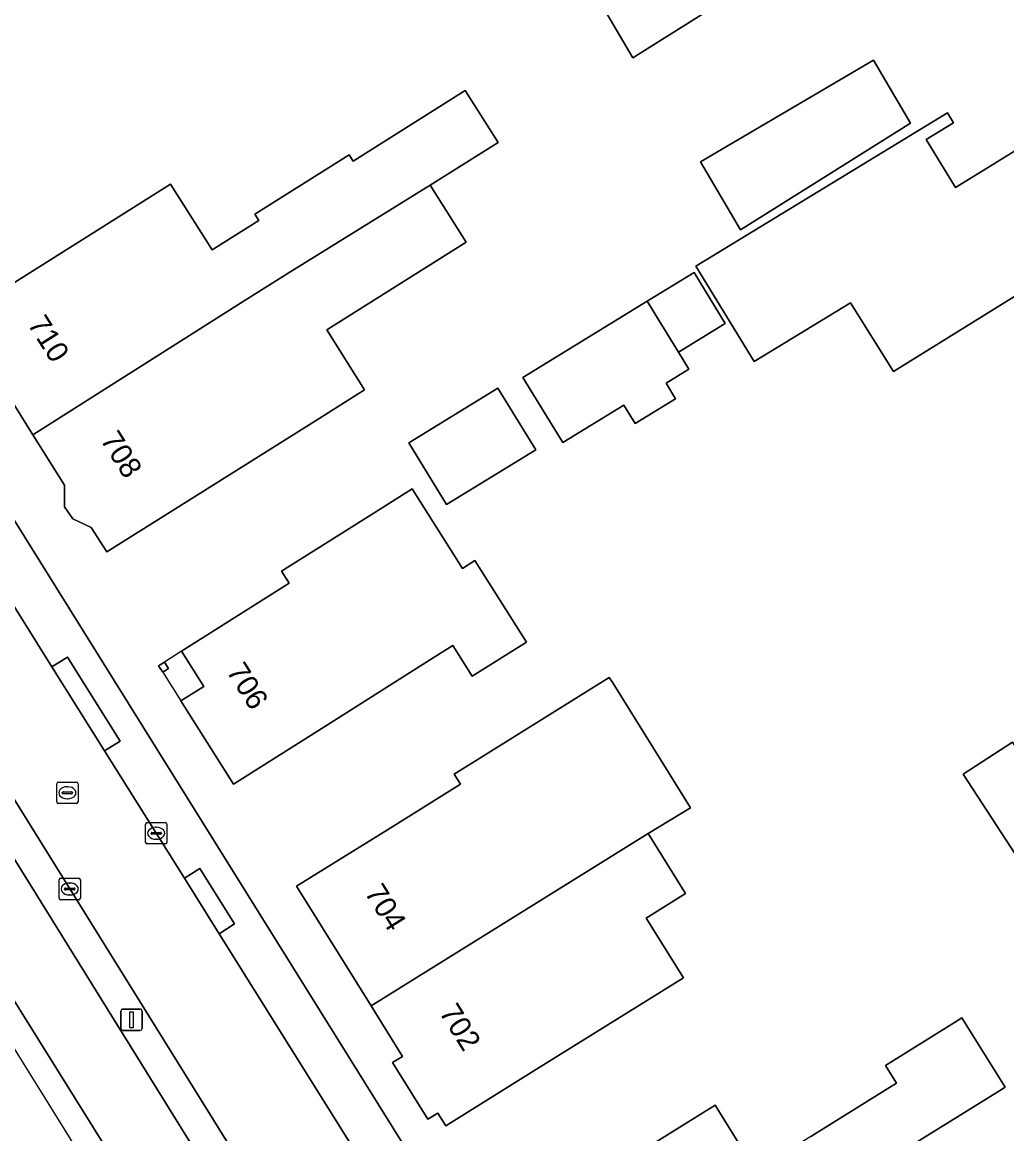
# Model space of a CAD drawing. Extents: x 158835 to 160077, y 386387 to 387778.
# Drawn here: x 159278.9 to 159325, y 386502 to 386554 of the extents above; entities that cross this region are included whole.
import ezdxf

# ---------------------------------------------------------------- set-up
doc = ezdxf.new("R2010")
doc.units = 0
for name, color, linetype in [('IMGEO_Berm_groen', 7, 'Continuous'), ('IMGEO_Erf', 7, 'Continuous'), ('IMGEO_Kolk', 7, 'Continuous'), ('IMGEO_Lichtmast', 7, 'Continuous'), ('IMGEO_Pand', 7, 'Continuous'), ('IMGEO_Pand_nummerreeks', 7, 'Continuous'), ('IMGEO_Pand_overbouw', 7, 'Continuous'), ('IMGEO_Rijbaan_lokaal_open', 7, 'Continuous'), ('IMGEO_Rijbaan_regionaal_gesloten', 7, 'Continuous'), ('IMGEO_Rioolput', 7, 'Continuous'), ('IMGEO_Voetpad_open', 7, 'Continuous')]:
    doc.layers.add(name, color=color, linetype=linetype)

msp = doc.modelspace()

# ---------------------------------------------------------------- linework, layer by layer
at = {"layer": 'IMGEO_Berm_groen'}
msp.add_lwpolyline([(159315.18, 386459.161), (159295.755, 386490.012), (159289.541, 386500), (159260.159, 386547.29), (159256.48, 386553.269), (159255.213, 386552.519), (159258.932, 386546.526), (159259.483, 386545.636), (159287.804, 386500), (159291.106, 386494.697), (159321.596, 386445.895)], dxfattribs=at)
at = {"layer": 'IMGEO_Erf'}
for points in [[(159242.178, 386588.93), (159258.715, 386562.329), (159267.344, 386548.729), (159297.72, 386500), (159350.037, 386416.075), (159354.981, 386419.093), (159355.61, 386419.476), (159355.898, 386419.653), (159356.079, 386419.763), (159378.488, 386433.441), (159394.408, 386443.649), (159394.408, 386443.649), (159438.145, 386502.052)], [(159315.823, 386501.878), (159319.305, 386504.047), (159319.841, 386504.381), (159319.324, 386505.211), (159322.554, 386507.223), (159322.898, 386507.437), (159324.917, 386504.195), (159324.573, 386503.981), (159320.807, 386501.636)], [(159306.189, 386500.139), (159311.349, 386503.353), (159313.262, 386500.283)]]:
    msp.add_lwpolyline(points, dxfattribs=at)
for points in [[(159313.722, 386560.307), (159315.455, 386557.36), (159307.505, 386552.36), (159305.63, 386555.547)], [(159318.761, 386552.248), (159320.494, 386549.301), (159312.544, 386544.301), (159310.669, 386547.488)], [(159301.198, 386548.394), (159298.028, 386546.399), (159299.707, 386543.73), (159293.194, 386539.633), (159294.96, 386536.827), (159292.781, 386535.456), (159282.898, 386529.236), (159282.175, 386530.385), (159281.313, 386530.786), (159280.921, 386531.351), (159280.926, 386532.369), (159279.444, 386534.724), (159277.456, 386537.883), (159276.716, 386538.221), (159276.291, 386538.901), (159276.295, 386539.728), (159275.987, 386540.218), (159285.886, 386546.448), (159287.821, 386543.372), (159290.009, 386544.749), (159289.821, 386545.047), (159294.233, 386547.824), (159294.42, 386547.526), (159299.666, 386550.828)], [(159322.223, 386549.778), (159322.505, 386549.317), (159321.223, 386548.533), (159322.604, 386546.293), (159323.89, 386547.086), (159326.716, 386548.827), (159326.981, 386548.404), (159327.868, 386546.988), (159328.387, 386547.275), (159330.245, 386544.227), (159319.691, 386537.673), (159317.69, 386540.897), (159313.172, 386538.149), (159310.454, 386542.605)], [(159310.366, 386542.313), (159311.826, 386539.932), (159309.636, 386538.589), (159310.123, 386537.796), (159309.056, 386537.141), (159309.506, 386536.407), (159307.612, 386535.246), (159307.088, 386536.099), (159304.237, 386534.351), (159302.364, 386537.404), (159308.177, 386540.969)], [(159301.194, 386536.9), (159302.963, 386534.016), (159298.795, 386531.46), (159297.026, 386534.343)], [(159300.114, 386528.832), (159302.523, 386525.021), (159299.988, 386523.418), (159299.079, 386524.855), (159298.046, 386524.202), (159293.051, 386521.044), (159288.824, 386518.372), (159286.361, 386522.269), (159287.434, 386522.948), (159286.398, 386524.588), (159291.434, 386527.771), (159291.077, 386528.336), (159295.304, 386531.008), (159297.183, 386532.196), (159299.539, 386528.469)], [(159285.594, 386524.08), (159285.787, 386523.776), (159285.516, 386523.605), (159285.324, 386523.909)], [(159309.872, 386517.788), (159310.202, 386517.258), (159308.226, 386516.065), (159309.975, 386513.254), (159308.127, 386512.103), (159309.867, 386509.309), (159303, 386505.033), (159298.755, 386502.389), (159298.385, 386502.983), (159297.918, 386502.692), (159296.269, 386505.341), (159296.735, 386505.632), (159295.266, 386507.992), (159291.777, 386513.597), (159296.022, 386516.241), (159299.438, 386518.368), (159299.146, 386518.838), (159306.403, 386523.359), (159306.561, 386523.105)], [(159325.408, 386515.082), (159322.962, 386518.841), (159325.259, 386520.336), (159327.705, 386516.577)]]:
    msp.add_lwpolyline(points, close=True, dxfattribs=at)
at = {"layer": 'IMGEO_Kolk'}
for p, q in [((159284.71, 386515.647), (159284.71, 386516.499)), ((159284.785, 386516.573), (159285.637, 386516.573)), ((159285.711, 386516.499), (159285.711, 386515.647)), ((159284.969, 386516.067), (159284.969, 386516.079)), ((159285.407, 386516.03), (159285.009, 386516.03)), ((159285.012, 386516.116), (159285.41, 386516.116)), ((159285.198, 386516.353), (159285.223, 386516.353)), ((159285.453, 386516.079), (159285.453, 386516.067)), ((159285.637, 386515.573), (159284.785, 386515.573)), ((159285.221, 386515.793), (159285.196, 386515.793)), ((159280.664, 386513.04), (159280.664, 386513.892)), ((159280.739, 386513.966), (159281.591, 386513.966)), ((159281.665, 386513.892), (159281.665, 386513.04)), ((159280.923, 386513.46), (159280.923, 386513.472)), ((159281.361, 386513.423), (159280.963, 386513.423)), ((159280.966, 386513.509), (159281.364, 386513.509)), ((159281.152, 386513.746), (159281.177, 386513.746)), ((159281.407, 386513.472), (159281.407, 386513.46)), ((159281.591, 386512.966), (159280.739, 386512.966)), ((159281.175, 386513.186), (159281.15, 386513.186))]:
    msp.add_line(p, q, dxfattribs=at)
for points in [[(159284.71, 386515.647), (159284.71, 386516.499)], [(159284.785, 386516.573), (159285.637, 386516.573)], [(159285.711, 386516.499), (159285.711, 386515.647)], [(159285.637, 386515.573), (159284.785, 386515.573)], [(159280.664, 386513.04), (159280.664, 386513.892)], [(159280.739, 386513.966), (159281.591, 386513.966)], [(159281.665, 386513.892), (159281.665, 386513.04)], [(159281.591, 386512.966), (159280.739, 386512.966)]]:
    msp.add_lwpolyline(points, dxfattribs=at)
for centre, radius, start, end in [((159284.787, 386516.497), 0.0765, 91.552, 178.448), ((159284.787, 386516.497), 0.0765, 91.552, 178.448), ((159285.635, 386516.497), 0.0765, 1.552, 88.448), ((159285.635, 386516.497), 0.0765, 1.552, 88.448), ((159285.009, 386516.076), 0.0403, 85.8775, 175.7526), ((159285.006, 386516.066), 0.0366, 178.938, 274.7102), ((159285.41, 386516.073), 0.043, 264.8664, 352.4533), ((159285.414, 386516.078), 0.0386, 1.7309, 96.639), ((159284.787, 386515.649), 0.0765, 181.552, 268.448), ((159284.787, 386515.649), 0.0765, 181.552, 268.448), ((159285.635, 386515.649), 0.0765, 271.552, 358.448), ((159285.635, 386515.649), 0.0765, 271.552, 358.448), ((159280.741, 386513.89), 0.0765, 91.552, 178.448), ((159280.741, 386513.89), 0.0765, 91.552, 178.448), ((159281.589, 386513.89), 0.0765, 1.552, 88.448), ((159281.589, 386513.89), 0.0765, 1.552, 88.448), ((159280.963, 386513.469), 0.0403, 85.8775, 175.7526), ((159280.96, 386513.459), 0.0366, 178.938, 274.7102), ((159281.364, 386513.466), 0.043, 264.8664, 352.4533), ((159281.368, 386513.471), 0.0386, 1.7309, 96.639), ((159280.741, 386513.042), 0.0765, 181.552, 268.448), ((159280.741, 386513.042), 0.0765, 181.552, 268.448), ((159281.589, 386513.042), 0.0765, 271.552, 358.448), ((159281.589, 386513.042), 0.0765, 271.552, 358.448)]:
    msp.add_arc(centre, radius, start, end, dxfattribs=at)
for centre, major_axis, ratio, start_param, end_param in [((159285.197, 386516.073), (-0.387, 0.002), 0.722429, 4.712389, 7.853982), ((159285.222, 386516.073), (-0.39, 0.002), 0.717154, 1.570796, 4.712389), ((159281.151, 386513.466), (-0.387, 0.002), 0.722429, 4.712389, 7.853982), ((159281.176, 386513.466), (-0.39, 0.002), 0.717154, 1.570796, 4.712389)]:
    msp.add_ellipse(centre, major_axis=major_axis, ratio=ratio, start_param=start_param, end_param=end_param, dxfattribs=at)
at = {"layer": 'IMGEO_Lichtmast'}
for p, q in [((159283.556, 386506.949), (159283.556, 386507.749)), ((159283.556, 386507.749), (159283.556, 386506.949)), ((159283.656, 386507.849), (159284.446, 386507.849)), ((159284.446, 386507.849), (159283.656, 386507.849)), ((159284.546, 386507.749), (159284.546, 386506.949)), ((159284.546, 386506.949), (159284.546, 386507.749)), ((159284.446, 386506.849), (159283.656, 386506.849)), ((159283.656, 386506.849), (159284.446, 386506.849))]:
    msp.add_line(p, q, dxfattribs=at)
msp.add_lwpolyline([(159283.976, 386507.724), (159284.126, 386507.724), (159284.126, 386506.974), (159283.976, 386506.974), (159283.976, 386507.724)], dxfattribs=at)
for centre, start, end in [((159283.656, 386507.749), 90, 180), ((159283.656, 386507.749), 90, 180), ((159284.446, 386507.749), 0, 90), ((159284.446, 386507.749), 360, 90), ((159283.656, 386506.949), 180, 270), ((159283.656, 386506.949), 180, 270), ((159284.446, 386506.949), 270, 0), ((159284.446, 386506.949), 270, 0)]:
    msp.add_arc(centre, 0.1, start, end, dxfattribs=at)
at = {"layer": 'IMGEO_Pand'}
for points in [[(159313.722, 386560.307), (159305.63, 386555.547), (159307.505, 386552.36), (159315.455, 386557.36)], [(159318.761, 386552.248), (159310.669, 386547.488), (159312.544, 386544.301), (159320.494, 386549.301)], [(159298.028, 386546.399), (159301.198, 386548.394), (159299.666, 386550.828), (159294.42, 386547.526), (159294.233, 386547.824), (159289.821, 386545.047), (159290.009, 386544.749), (159287.821, 386543.372), (159285.886, 386546.448), (159275.987, 386540.218), (159276.295, 386539.728), (159276.291, 386538.901), (159276.716, 386538.221), (159277.456, 386537.883), (159279.444, 386534.724), (159289.32, 386540.99), (159291.51, 386542.365)], [(159322.604, 386546.293), (159321.223, 386548.533), (159322.505, 386549.317), (159322.223, 386549.778), (159310.454, 386542.605), (159313.172, 386538.149), (159317.69, 386540.897), (159319.691, 386537.673), (159330.245, 386544.227), (159328.387, 386547.275), (159327.868, 386546.988), (159326.981, 386548.404), (159326.716, 386548.827), (159323.89, 386547.086)], [(159293.194, 386539.633), (159299.707, 386543.73), (159298.028, 386546.399), (159291.51, 386542.365), (159289.32, 386540.99), (159279.444, 386534.724), (159280.926, 386532.369), (159280.921, 386531.351), (159281.313, 386530.786), (159282.175, 386530.385), (159282.898, 386529.236), (159292.781, 386535.456), (159294.96, 386536.827)], [(159308.177, 386540.969), (159309.636, 386538.589), (159311.826, 386539.932), (159310.366, 386542.313)], [(159309.636, 386538.589), (159308.177, 386540.969), (159302.364, 386537.404), (159304.237, 386534.351), (159307.088, 386536.099), (159307.612, 386535.246), (159309.506, 386536.407), (159309.056, 386537.141), (159310.123, 386537.796)], [(159301.194, 386536.9), (159297.026, 386534.343), (159298.795, 386531.46), (159302.963, 386534.016)], [(159300.114, 386528.832), (159299.539, 386528.469), (159297.183, 386532.196), (159295.304, 386531.008), (159291.077, 386528.336), (159291.434, 386527.771), (159286.398, 386524.588), (159287.434, 386522.948), (159286.361, 386522.269), (159288.824, 386518.372), (159293.051, 386521.044), (159298.046, 386524.202), (159299.079, 386524.855), (159299.988, 386523.418), (159302.523, 386525.021)], [(159285.594, 386524.08), (159285.324, 386523.909), (159285.516, 386523.605), (159285.787, 386523.776)], [(159309.872, 386517.788), (159306.561, 386523.105), (159306.403, 386523.359), (159299.146, 386518.838), (159299.438, 386518.368), (159296.022, 386516.241), (159291.777, 386513.597), (159295.266, 386507.992), (159308.226, 386516.065), (159310.202, 386517.258)], [(159325.408, 386515.082), (159327.705, 386516.577), (159325.259, 386520.336), (159322.962, 386518.841)], [(159309.867, 386509.309), (159308.127, 386512.103), (159309.975, 386513.254), (159308.226, 386516.065), (159295.266, 386507.992), (159296.735, 386505.632), (159296.269, 386505.341), (159297.918, 386502.692), (159298.385, 386502.983), (159298.755, 386502.389), (159303, 386505.033)], [(159324.573, 386503.981), (159324.917, 386504.195), (159322.898, 386507.437), (159322.554, 386507.223), (159319.324, 386505.211), (159319.841, 386504.381), (159319.305, 386504.047), (159315.823, 386501.878), (159313.262, 386500.283), (159311.349, 386503.353), (159306.189, 386500.139), (159305.966, 386500), (159301.945, 386497.495), (159302.305, 386496.917), (159302.037, 386496.149), (159303.001, 386494.6), (159303.779, 386494.551), (159304.125, 386493.996), (159304.392, 386494.162), (159305.584, 386492.249), (159317.395, 386499.355), (159317.325, 386499.468), (159320.807, 386501.636)]]:
    msp.add_lwpolyline(points, close=True, dxfattribs=at)
at = {"layer": 'IMGEO_Pand_overbouw'}
msp.add_lwpolyline([(159286.398, 386524.588), (159285.594, 386524.08), (159285.787, 386523.776), (159285.516, 386523.605), (159286.361, 386522.269), (159287.434, 386522.948)], close=True, dxfattribs=at)
at = {"layer": 'IMGEO_Rijbaan_lokaal_open'}
for points in [[(159315.365, 386467.935), (159309.005, 386478.076), (159304.878, 386484.657), (159303.63, 386486.647), (159298.588, 386494.701), (159295.271, 386500), (159294.836, 386500.695), (159288.15, 386511.374), (159286.529, 386513.965), (159282.795, 386519.928), (159280.335, 386523.857), (159276.367, 386530.196), (159263.845, 386550.455), (159253.667, 386567.296)], [(159253.383, 386558.225), (159256.331, 386553.511), (159256.48, 386553.269), (159260.159, 386547.29), (159289.541, 386500), (159295.755, 386490.012), (159315.18, 386459.161)]]:
    msp.add_lwpolyline(points, dxfattribs=at)
at = {"layer": 'IMGEO_Rijbaan_regionaal_gesloten'}
for points in [[(159235.681, 386584.197), (159233.96, 386587.187), (159230.609, 386585.166), (159302.571, 386469.726), (159345.081, 386401.546), (159348.223, 386403.503), (159321.596, 386445.895), (159291.106, 386494.697), (159287.804, 386500), (159259.483, 386545.636), (159258.932, 386546.526), (159255.213, 386552.519), (159255.058, 386552.765), (159249.738, 386561.333), (159239.908, 386577.097), (159238.851, 386578.829)], [(159343.877, 386400.796), (159345.081, 386401.546), (159302.571, 386469.726), (159230.609, 386585.166), (159229.657, 386584.591), (159254.183, 386545.243)]]:
    msp.add_lwpolyline(points, close=True, dxfattribs=at)
at = {"layer": 'IMGEO_Rioolput'}
for p, q in [((159280.556, 386517.542), (159280.556, 386518.394)), ((159280.631, 386518.468), (159281.483, 386518.468)), ((159280.815, 386517.962), (159280.815, 386517.974)), ((159280.858, 386518.011), (159281.256, 386518.011)), ((159281.044, 386518.248), (159281.069, 386518.248)), ((159281.299, 386517.974), (159281.299, 386517.962)), ((159281.557, 386518.394), (159281.557, 386517.542)), ((159281.483, 386517.468), (159280.631, 386517.468)), ((159281.253, 386517.925), (159280.855, 386517.925)), ((159281.067, 386517.688), (159281.042, 386517.688))]:
    msp.add_line(p, q, dxfattribs=at)
for points in [[(159280.556, 386517.542), (159280.556, 386518.394)], [(159280.631, 386518.468), (159281.483, 386518.468)], [(159281.557, 386518.394), (159281.557, 386517.542)], [(159281.483, 386517.468), (159280.631, 386517.468)]]:
    msp.add_lwpolyline(points, dxfattribs=at)
for centre, radius, start, end in [((159280.633, 386518.392), 0.0765, 91.552, 178.448), ((159280.633, 386518.392), 0.0765, 91.552, 178.448), ((159280.855, 386517.971), 0.0403, 85.8775, 175.7526), ((159281.26, 386517.973), 0.0386, 1.7309, 96.639), ((159281.481, 386518.392), 0.0765, 1.552, 88.448), ((159281.481, 386518.392), 0.0765, 1.552, 88.448), ((159280.633, 386517.544), 0.0765, 181.552, 268.448), ((159280.633, 386517.544), 0.0765, 181.552, 268.448), ((159280.852, 386517.961), 0.0366, 178.938, 274.7102), ((159281.256, 386517.968), 0.043, 264.8664, 352.4533), ((159281.481, 386517.544), 0.0765, 271.552, 358.448), ((159281.481, 386517.544), 0.0765, 271.552, 358.448)]:
    msp.add_arc(centre, radius, start, end, dxfattribs=at)
for centre, major_axis, ratio, start_param, end_param in [((159281.043, 386517.968), (-0.387, 0.002), 0.722429, 4.712389, 7.853982), ((159281.068, 386517.968), (-0.39, 0.002), 0.717154, 1.570796, 4.712389)]:
    msp.add_ellipse(centre, major_axis=major_axis, ratio=ratio, start_param=start_param, end_param=end_param, dxfattribs=at)
at = {"layer": 'IMGEO_Voetpad_open'}
for points in [[(159297.72, 386500), (159267.344, 386548.729), (159258.715, 386562.329), (159242.178, 386588.93)], [(159253.667, 386567.296), (159263.845, 386550.455), (159276.367, 386530.196), (159280.335, 386523.857), (159281.064, 386524.313), (159283.524, 386520.384), (159282.795, 386519.928), (159286.529, 386513.965), (159287.258, 386514.421), (159288.879, 386511.83), (159288.15, 386511.374), (159294.836, 386500.695), (159295.718, 386501.247), (159299.47, 386495.253), (159298.588, 386494.701), (159303.63, 386486.647), (159304.878, 386484.657), (159305.759, 386485.21), (159309.886, 386478.629), (159309.005, 386478.076), (159315.365, 386467.935)]]:
    msp.add_lwpolyline(points, dxfattribs=at)
for points in [[(159280.335, 386523.857), (159282.795, 386519.928), (159283.524, 386520.384), (159281.064, 386524.313)], [(159286.529, 386513.965), (159288.15, 386511.374), (159288.879, 386511.83), (159287.258, 386514.421)]]:
    msp.add_lwpolyline(points, close=True, dxfattribs=at)

# ---------------------------------------------------------------- texts
at = {"layer": 'IMGEO_Pand_nummerreeks'}
for s, rotation, p in [('710', 302.1828, (159279.165, 386539.901)), ('708', 302.1828, (159282.572, 386534.488)), ('706', 302.2974, (159288.467, 386523.653)), ('704', 301.9078, (159294.932, 386513.298)), ('702', 301.9078, (159298.42, 386507.696))]:
    msp.add_text(s, height=1, rotation=rotation, dxfattribs=at).set_placement(p)

doc.saveas('drawing.dxf')
